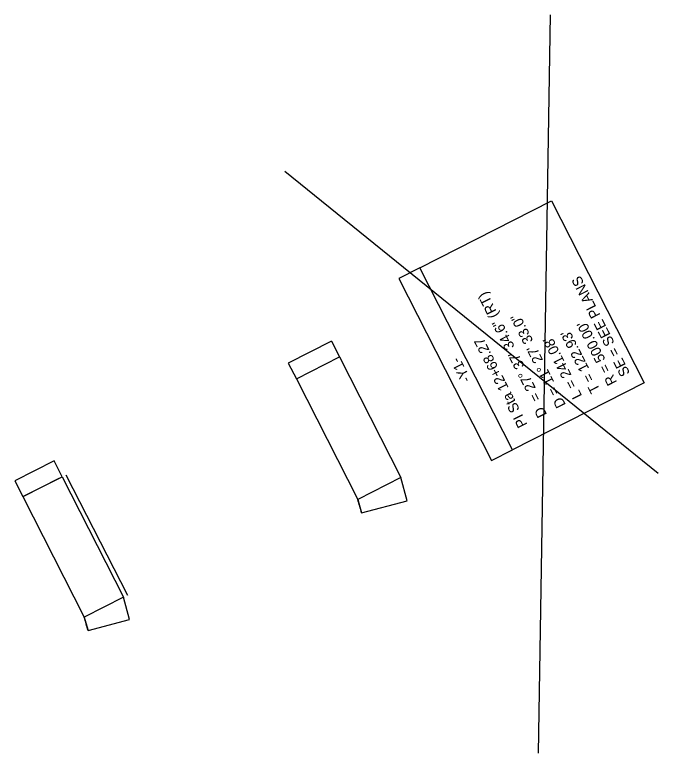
# Model space of a CAD drawing. Extents: x 557583 to 560285, y 513145 to 516544.
# Drawn here: x 559500 to 559938, y 513145 to 513649 of the extents above; entities that cross this region are included whole.
import ezdxf

# ---------------------------------------------------------------- set-up
doc = ezdxf.new("R2010")
doc.units = 0
for name, color, linetype in [('Exist Environmental Wetland Boundary Cogo Point CELL', 7, 'Continuous'), ('Exist Hydro Jurisdictional Stream or Body of Water NEU Mitigable', 7, 'Continuous'), ('Exist Hydro Jurisdictional Stream or Body of Water NEU Mitigable Cogo Number', 7, 'Continuous'), ('Scratch_Level_8', 7, 'Continuous')]:
    doc.layers.add(name, color=color, linetype=linetype)

msp = doc.modelspace()

# ---------------------------------------------------------------- linework, layer by layer
at = {"layer": 'Exist Environmental Wetland Boundary Cogo Point CELL'}
for points in [[(559838.86, 513352.22), (559775.72, 513476.24), (559865.24, 513521.81), (559928.38, 513397.79)], [(559838.86, 513352.22), (559775.72, 513476.24), (559761.38, 513468.94), (559824.52, 513344.92)]]:
    msp.add_lwpolyline(points, close=True, dxfattribs=at)
at = {"layer": 'Exist Hydro Jurisdictional Stream or Body of Water NEU Mitigable Cogo Number'}
for p, q in [((559715.56, 513426.14), (559686.15, 513411.17)), ((559715.56, 513426.14), (559721, 513415.45)), ((559691.6, 513400.48), (559721, 513415.45)), ((559721, 513415.45), (559762.83, 513333.29)), ((559686.15, 513411.17), (559691.6, 513400.48)), ((559691.6, 513400.48), (559733.42, 513318.32)), ((559526.63, 513344.6), (559499.9, 513330.99)), ((559532.07, 513333.91), (559526.63, 513344.6)), ((559505.34, 513320.29), (559532.08, 513333.9)), ((559505.95, 513320.6), (559530.02, 513332.86)), ((559532.08, 513333.9), (559573.91, 513251.75)), ((559534.75, 513335.26), (559576.58, 513253.11)), ((559762.83, 513333.29), (559733.42, 513318.32)), ((559767.04, 513317.49), (559762.83, 513333.29)), ((559499.9, 513330.99), (559505.34, 513320.29)), ((559505.34, 513320.29), (559547.17, 513238.14)), ((559733.42, 513318.32), (559736.03, 513309.24)), ((559736.03, 513309.24), (559767.04, 513317.49)), ((559573.91, 513251.75), (559547.17, 513238.14)), ((559577.95, 513236.55), (559573.91, 513251.75)), ((559547.17, 513238.14), (559549.78, 513229.06)), ((559549.78, 513229.06), (559577.95, 513236.55))]:
    msp.add_line(p, q, dxfattribs=at)
for centre in [(559506.04, 513248.05), (559319.78, 513167.86)]:
    msp.add_arc(centre, 238, 14.8991, 17.1739, dxfattribs=at)
at = {"layer": 'Scratch_Level_8'}
for p, q in [((559856.58, 513145.49), (559864.61, 513648.61)), ((559683.85, 513542.01), (559937.99, 513336.28))]:
    msp.add_line(p, q, dxfattribs=at)

# ---------------------------------------------------------------- texts
at = {"layer": 'Exist Hydro Jurisdictional Stream or Body of Water NEU Mitigable'}
for s, p in [('SE = SEE PLANS', (559918.99, 513404.33)), ('= 27%%d 37\' 34.6" (RT)', (559858.43, 513387.11)), ('D = 11%%d 27\' 33.0"', (559875.26, 513382.83)), ("R = 500.00'", (559910.14, 513398.2)), ("T = 122.93'", (559898.6, 513392.89)), ('PI Sta 12+68.27', (559849.11, 513369.39)), ("L = 241.08'", (559886.33, 513388.98)), ('-Y1-', (559810.59, 513400.14)), ('D', (559862.46, 513376.23))]:
    msp.add_text(s, height=7, rotation=116.9819, dxfattribs=at).set_placement(p)

doc.saveas('drawing.dxf')
